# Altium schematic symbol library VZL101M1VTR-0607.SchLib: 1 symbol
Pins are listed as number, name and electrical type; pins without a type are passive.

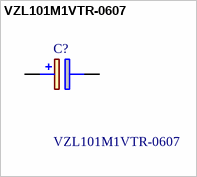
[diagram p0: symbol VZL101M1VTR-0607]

## VZL101M1VTR-0607
designator C?
Aluminum Electrolytic Capacitors - SMD 100uF 35 Volts 20%; Manufacturer_Name: Lelon; Geometry.Height: 10.5mm
footprint CAPAE830X1050N
pins: 1 +, 2 -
